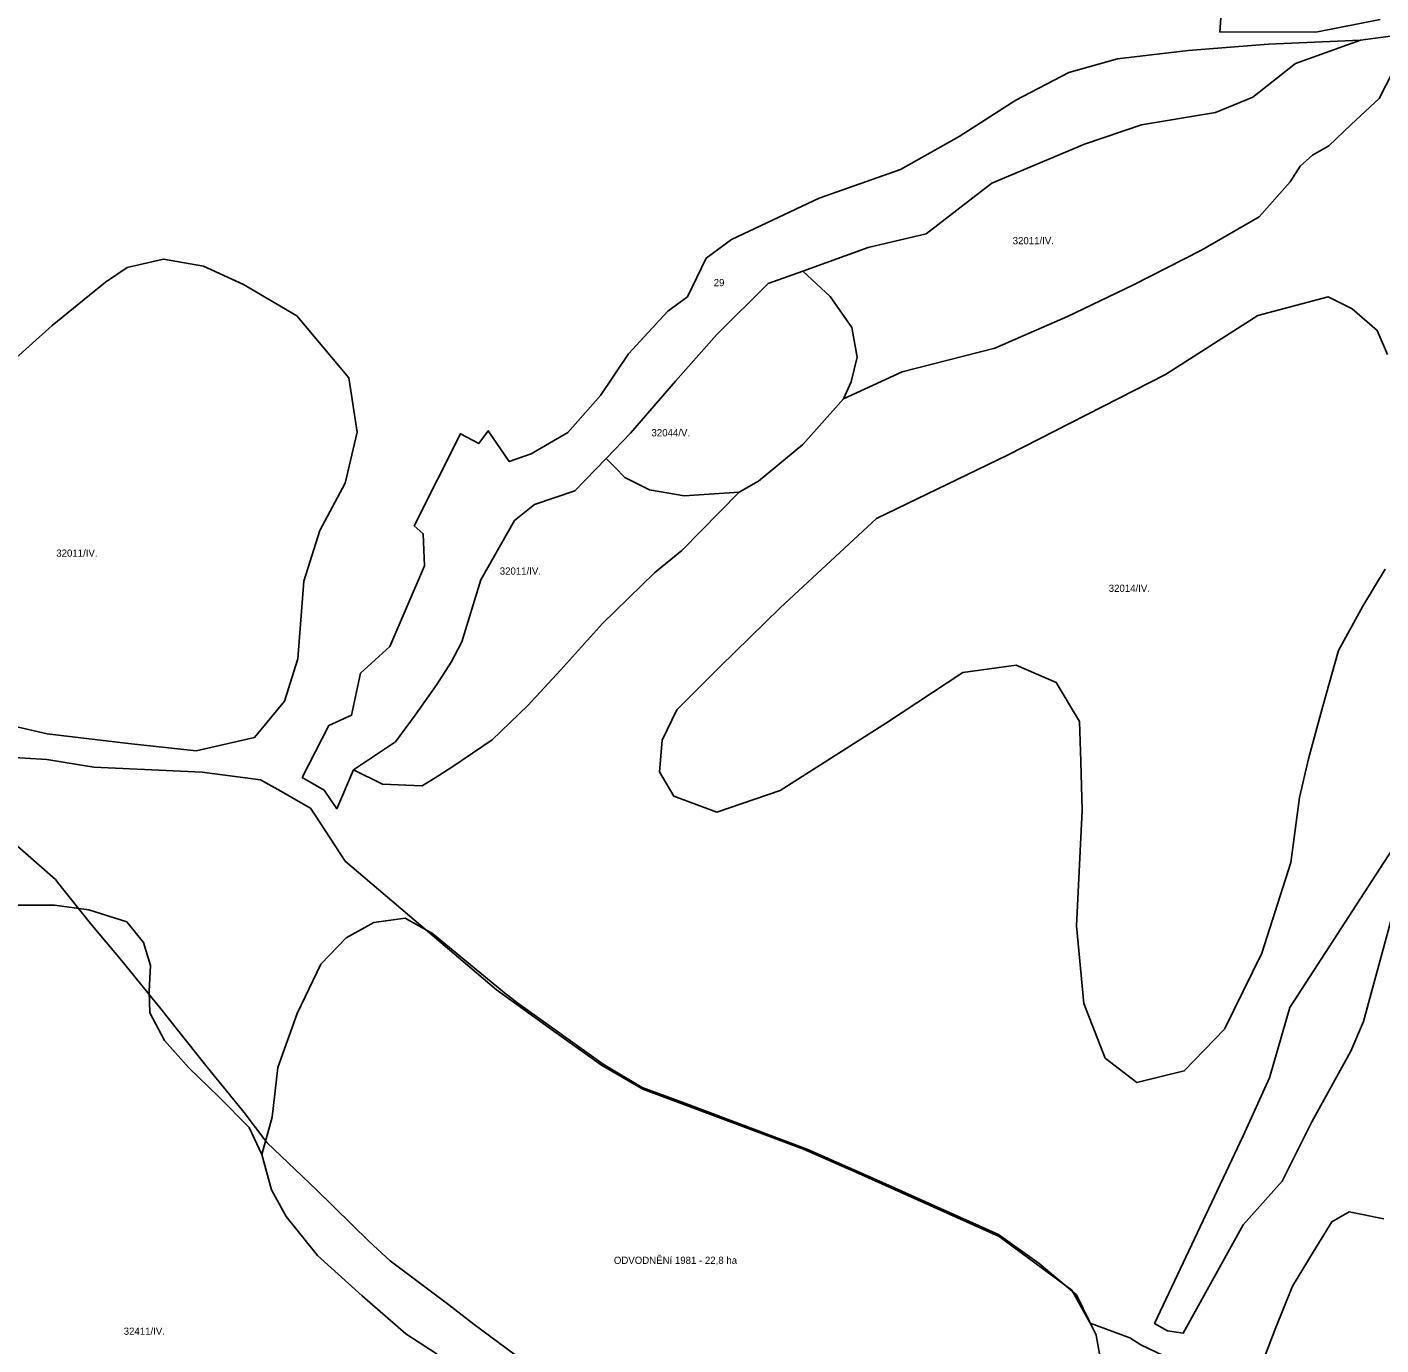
# Model space of a CAD drawing. Extents: x -521621 to -516761, y -1190184 to -1184927.
# Drawn here: x -518211 to -517460, y -1187665 to -1186934 of the extents above; entities that cross this region are included whole.
import ezdxf

# ---------------------------------------------------------------- set-up
doc = ezdxf.new("R2010")
doc.units = 0
doc.layers.add('BPEJ_s', color=7, linetype='Continuous')
doc.layers.add('odvodneni_s', color=7, linetype='Continuous')

msp = doc.modelspace()

# ---------------------------------------------------------------- linework, layer by layer
at = {"layer": 'BPEJ_s'}
for points in [[(-517449.03, -1186951.31), (-517460.58, -1186973.53), (-517476.03, -1186988.1), (-517488.46, -1186999.83), (-517497.52, -1187004.99), (-517504.38, -1187011.23), (-517509.98, -1187019.85), (-517527.2, -1187039.23), (-517559.06, -1187057.76), (-517597.31, -1187077.14), (-517633.59, -1187094.62), (-517673.9, -1187112.1), (-517725.3, -1187125.21), (-517757.89, -1187140.33), (-517780.4, -1187165.55), (-517804.92, -1187186.05), (-517815.67, -1187192.1), (-517847.58, -1187224.37), (-517862.7, -1187236.81), (-517891.59, -1187265.04), (-517914.77, -1187290.93), (-517932.91, -1187310.42), (-517952.73, -1187329.58), (-517974.57, -1187344.37), (-517982.97, -1187349.75), (-517991.7, -1187355.13), (-518013.54, -1187354.12), (-518029.72, -1187346.19), (-518038.98, -1187367.79), (-518045.96, -1187357.39), (-518058.12, -1187350.38), (-518043.45, -1187321.5), (-518030.79, -1187315.94), (-518025.93, -1187292.6), (-518009.65, -1187277.77), (-517990.31, -1187233), (-517991.03, -1187215.19), (-517996.11, -1187210.68), (-517970.35, -1187159.68), (-517960.2, -1187165.13), (-517954.93, -1187157.98), (-517943.27, -1187175.11), (-517931.05, -1187170.78), (-517910.74, -1187158.92), (-517892.69, -1187138.41), (-517877.03, -1187115.33), (-517855.2, -1187091.6), (-517844.41, -1187083.69), (-517834, -1187062.21), (-517819.95, -1187051.92), (-517771.39, -1187028.94), (-517726.14, -1187013.04), (-517693.57, -1186994.78), (-517662.24, -1186974.5), (-517632.81, -1186959.09), (-517605.84, -1186951.66), (-517566.49, -1186946.97), (-517521.9, -1186943.39), (-517470.99, -1186941.19), (-517445.99, -1186937.81)], [(-517449.03, -1186951.31), (-517460.58, -1186973.53), (-517476.03, -1186988.1), (-517488.46, -1186999.83), (-517497.52, -1187004.99), (-517504.38, -1187011.23), (-517509.98, -1187019.85), (-517527.2, -1187039.23), (-517559.06, -1187057.76), (-517597.31, -1187077.14), (-517633.59, -1187094.62), (-517673.9, -1187112.1), (-517725.3, -1187125.21), (-517757.89, -1187140.33), (-517753.52, -1187130.92), (-517750.16, -1187117.14), (-517753.18, -1187100.67), (-517765.28, -1187083.53), (-517780.4, -1187069.41), (-517744.18, -1187056.27), (-517711.98, -1187048.8), (-517675.47, -1187020.56), (-517624, -1186999.04), (-517592.36, -1186988.3), (-517551.35, -1186981.41), (-517530.71, -1186972.87), (-517507.04, -1186954.14), (-517470.99, -1186941.19), (-517445.99, -1186937.81)], [(-518222.49, -1187122.52), (-518196.96, -1187099.66), (-518167.39, -1187075.46), (-518155.3, -1187067.39), (-518135.14, -1187062.69), (-518112.97, -1187066.72), (-518090.8, -1187076.81), (-518061.24, -1187094.29), (-518032.35, -1187128.57), (-518027.65, -1187158.82), (-518034.36, -1187187.06), (-518048.47, -1187213.28), (-518057.21, -1187241.51), (-518060.57, -1187284.54), (-518067.96, -1187308.07), (-518084.75, -1187328.24), (-518117, -1187335.63), (-518154.63, -1187331.6), (-518199.64, -1187326.22), (-518235.25, -1187318.15)], [(-518222.49, -1187122.52), (-518196.96, -1187099.66), (-518167.39, -1187075.46), (-518155.3, -1187067.39), (-518135.14, -1187062.69), (-518112.97, -1187066.72), (-518090.8, -1187076.81), (-518061.24, -1187094.29), (-518032.35, -1187128.57), (-518027.65, -1187158.82), (-518034.36, -1187187.06), (-518048.47, -1187213.28), (-518057.21, -1187241.51), (-518060.57, -1187284.54), (-518067.96, -1187308.07), (-518084.75, -1187328.24), (-518117, -1187335.63), (-518154.63, -1187331.6), (-518199.64, -1187326.22), (-518235.25, -1187318.15)], [(-517457.21, -1187234.78), (-517469.69, -1187255.33), (-517483.07, -1187279.92), (-517491.81, -1187310.79), (-517499.72, -1187340.02), (-517504.83, -1187361.61), (-517509.62, -1187397.54), (-517525.58, -1187447.85), (-517546.33, -1187490.17), (-517568.67, -1187513.33), (-517595.01, -1187519.72), (-517612.56, -1187506.14), (-517619.74, -1187487.78), (-517624.53, -1187475.8), (-517628.52, -1187432.68), (-517625.33, -1187368.8), (-517626.13, -1187341.65), (-517626.93, -1187319.29), (-517639.7, -1187297.73), (-517662.04, -1187288.14), (-517691.57, -1187292.14), (-517733.86, -1187320.08), (-517792.92, -1187357.61), (-517828.03, -1187369.59), (-517851.97, -1187360.81), (-517859.95, -1187347.23), (-517858.36, -1187329.67), (-517850.38, -1187312.9), (-517826.44, -1187288.94), (-517792.92, -1187256.2), (-517739.45, -1187206.69), (-517666.83, -1187171.56), (-517579.04, -1187126.84), (-517527.97, -1187094.1), (-517488.87, -1187083.72), (-517475.57, -1187090.31), (-517461.64, -1187102.35), (-517455.94, -1187115.66)], [(-517455.94, -1187115.66), (-517461.64, -1187102.35), (-517475.57, -1187090.31), (-517488.87, -1187083.72), (-517527.97, -1187094.1), (-517579.04, -1187126.84), (-517666.83, -1187171.56), (-517739.45, -1187206.69), (-517792.92, -1187256.2), (-517826.44, -1187288.94), (-517850.38, -1187312.9), (-517858.36, -1187329.67), (-517859.95, -1187347.23), (-517851.97, -1187360.81), (-517828.03, -1187369.59), (-517792.92, -1187357.61), (-517733.86, -1187320.08), (-517691.57, -1187292.14), (-517662.04, -1187288.14), (-517639.7, -1187297.73), (-517626.93, -1187319.29), (-517626.13, -1187341.65), (-517625.33, -1187368.8), (-517628.52, -1187432.68), (-517624.53, -1187475.8), (-517619.74, -1187487.78), (-517612.56, -1187506.14), (-517595.01, -1187519.72), (-517568.67, -1187513.33), (-517546.33, -1187490.17), (-517525.58, -1187447.85), (-517509.62, -1187397.54), (-517504.83, -1187361.61), (-517499.72, -1187340.02), (-517491.81, -1187310.79), (-517483.07, -1187279.92), (-517469.69, -1187255.33), (-517457.21, -1187234.78)], [(-517451.95, -1187422.51), (-517469.3, -1187485.9), (-517476.24, -1187502.4), (-517497.93, -1187541.48), (-517514.42, -1187574.48), (-517536.11, -1187598.79), (-517569.29, -1187658.8), (-517578.06, -1187657.49), (-517585.17, -1187653.55), (-517536.11, -1187549.29), (-517521.36, -1187517.16), (-517510.08, -1187478.08), (-517399, -1187306.68)], [(-517399, -1187306.68), (-517510.08, -1187478.08), (-517521.36, -1187517.16), (-517536.11, -1187549.29), (-517585.17, -1187653.55), (-517578.06, -1187657.49), (-517569.29, -1187658.8), (-517536.11, -1187598.79), (-517514.42, -1187574.48), (-517497.93, -1187541.48), (-517476.24, -1187502.4), (-517469.3, -1187485.9), (-517451.95, -1187422.51)], [(-518219.49, -1187421.38), (-518195.69, -1187421.38), (-518176.51, -1187423.87), (-518155.55, -1187430.62), (-518146.31, -1187442), (-518142.41, -1187454.79), (-518143.12, -1187469.01), (-518142.76, -1187481.09), (-518134.59, -1187496.38), (-518121.09, -1187511.66), (-518104.4, -1187527.66), (-518087.7, -1187544.72), (-518080.6, -1187559.65), (-518075.27, -1187579.19), (-518067.1, -1187594.12), (-518049.7, -1187615.8), (-518024.83, -1187638.2), (-518000.68, -1187659.17), (-517983.27, -1187670.54)], [(-517612.9, -1187685.91), (-517617.66, -1187660.01), (-517628.56, -1187637.52), (-517649.24, -1187620.23), (-517671.84, -1187604.16), (-517736.22, -1187575.2), (-517777.6, -1187556.89), (-517845.83, -1187531.14), (-517869.6, -1187522.41), (-517891.18, -1187509.56), (-517938.45, -1187475.62), (-517945.94, -1187470), (-517985.88, -1187436.93), (-518001.03, -1187428.49), (-518018.44, -1187430.98), (-518033.71, -1187439.51), (-518047.92, -1187454.08), (-518061.06, -1187481.45), (-518071.72, -1187511.31), (-518074.92, -1187539.03), (-518080.6, -1187559.65), (-518087.7, -1187544.72), (-518104.4, -1187527.66), (-518121.09, -1187511.66), (-518134.59, -1187496.38), (-518142.76, -1187481.09), (-518143.12, -1187469.01), (-518142.41, -1187454.79), (-518146.31, -1187442), (-518155.55, -1187430.62), (-518176.51, -1187423.87), (-518195.69, -1187421.38), (-518219.49, -1187421.38)], [(-517983.27, -1187670.54), (-518000.68, -1187659.17), (-518024.83, -1187638.2), (-518049.7, -1187615.8), (-518067.1, -1187594.12), (-518075.27, -1187579.19), (-518080.6, -1187559.65), (-518074.92, -1187539.03), (-518071.72, -1187511.31), (-518061.06, -1187481.45), (-518047.92, -1187454.08), (-518033.71, -1187439.51), (-518018.44, -1187430.98), (-518001.03, -1187428.49), (-517985.88, -1187436.93), (-517945.94, -1187470), (-517938.45, -1187475.62), (-517891.18, -1187509.56), (-517869.6, -1187522.41), (-517845.83, -1187531.14), (-517777.6, -1187556.89), (-517736.22, -1187575.2), (-517671.84, -1187604.16), (-517649.24, -1187620.23), (-517628.56, -1187637.52), (-517617.66, -1187660.01), (-517612.9, -1187685.91)], [(-517540.69, -1187715.22), (-517518.21, -1187656.6), (-517508.68, -1187632.75), (-517497.2, -1187613.83), (-517486.81, -1187597.03), (-517477.21, -1187591.43), (-517458.02, -1187595.43)], [(-517458.02, -1187595.43), (-517477.21, -1187591.43), (-517486.81, -1187597.03), (-517497.2, -1187613.83), (-517508.68, -1187632.75), (-517518.21, -1187656.6), (-517540.69, -1187715.22)]]:
    msp.add_lwpolyline(points, dxfattribs=at)
for points in [[(-518029.72, -1187346.19), (-518038.98, -1187367.79), (-518045.96, -1187357.39), (-518058.12, -1187350.38), (-518043.45, -1187321.5), (-518030.79, -1187315.94), (-518025.93, -1187292.6), (-518009.65, -1187277.77), (-517990.31, -1187233), (-517991.03, -1187215.19), (-517996.11, -1187210.68), (-517970.35, -1187159.68), (-517960.2, -1187165.13), (-517954.93, -1187157.98), (-517943.27, -1187175.11), (-517931.05, -1187170.78), (-517910.74, -1187158.92), (-517892.69, -1187138.41), (-517877.03, -1187115.33), (-517855.2, -1187091.6), (-517844.41, -1187083.69), (-517834, -1187062.21), (-517819.95, -1187051.92), (-517771.39, -1187028.94), (-517726.14, -1187013.04), (-517693.57, -1186994.78), (-517662.24, -1186974.5), (-517632.81, -1186959.09), (-517605.84, -1186951.66), (-517566.49, -1186946.97), (-517521.9, -1186943.39), (-517470.99, -1186941.19), (-517507.04, -1186954.14), (-517530.71, -1186972.87), (-517551.35, -1186981.41), (-517592.36, -1186988.3), (-517624, -1186999.04), (-517675.47, -1187020.56), (-517711.98, -1187048.8), (-517744.18, -1187056.27), (-517780.4, -1187069.41), (-517799.61, -1187076.37), (-517828.16, -1187104.61), (-517851.06, -1187130.52), (-517875.94, -1187159.33), (-517889.51, -1187173.34), (-517906.94, -1187191.35), (-517929.34, -1187198.96), (-517940.34, -1187207.76), (-517959.14, -1187240.79), (-517969.54, -1187275.21), (-517975.54, -1187286.42), (-517983.54, -1187298.83), (-517995.59, -1187315.89), (-518006.5, -1187330.73)], [(-517889.51, -1187173.34), (-517875.94, -1187159.33), (-517851.06, -1187130.52), (-517828.16, -1187104.61), (-517799.61, -1187076.37), (-517780.4, -1187069.41), (-517765.28, -1187083.53), (-517753.18, -1187100.67), (-517750.16, -1187117.14), (-517753.52, -1187130.92), (-517757.89, -1187140.33), (-517780.4, -1187165.55), (-517804.92, -1187186.05), (-517815.67, -1187192.1), (-517846.24, -1187194.12), (-517865.39, -1187190.76), (-517879.16, -1187184.03), (-517884.54, -1187178.32)], [(-518029.72, -1187346.19), (-518006.5, -1187330.73), (-517995.59, -1187315.89), (-517983.54, -1187298.83), (-517975.54, -1187286.42), (-517969.54, -1187275.21), (-517959.14, -1187240.79), (-517940.34, -1187207.76), (-517929.34, -1187198.96), (-517906.94, -1187191.35), (-517889.51, -1187173.34), (-517884.54, -1187178.32), (-517879.16, -1187184.03), (-517865.39, -1187190.76), (-517846.24, -1187194.12), (-517815.67, -1187192.1), (-517847.58, -1187224.37), (-517862.7, -1187236.81), (-517891.59, -1187265.04), (-517914.77, -1187290.93), (-517932.91, -1187310.42), (-517952.73, -1187329.58), (-517974.57, -1187344.37), (-517982.97, -1187349.75), (-517991.7, -1187355.13), (-518013.54, -1187354.12)]]:
    msp.add_lwpolyline(points, close=True, dxfattribs=at)
at = {"layer": 'odvodneni_s'}
for points in [[(-517543.45, -1186858.01), (-517548.94, -1186936.72), (-517494.86, -1186936.67), (-517460.04, -1186929.71)], [(-518195.14, -1187407), (-518237.7, -1187369.82), (-518236.16, -1187338.27), (-518199.87, -1187340.38), (-518173.8, -1187344.62), (-518113.74, -1187347.57), (-518081.32, -1187351.71), (-518067.11, -1187359.78)], [(-518067.11, -1187359.78), (-518063.05, -1187362.09), (-518053.59, -1187367.46), (-518051.08, -1187371.3)], [(-518051.08, -1187371.3), (-518034.34, -1187396.85)], [(-518034.34, -1187396.85), (-517950.34, -1187468.33)], [(-518191.26, -1187411.98), (-518193.24, -1187409.43), (-518195.14, -1187407)], [(-518175.58, -1187431.48), (-518191.26, -1187411.98)], [(-518158.37, -1187452.16), (-518175.58, -1187431.48)], [(-518137.31, -1187477.94), (-518158.37, -1187452.16)], [(-517950.34, -1187468.33), (-517921.14, -1187489.42)], [(-518111.61, -1187510.19), (-518137.31, -1187477.94)], [(-517921.14, -1187489.42), (-517892.03, -1187510.14)], [(-518090.47, -1187536.35), (-518111.61, -1187510.19)], [(-517892.03, -1187510.14), (-517869.1, -1187523.41)], [(-517869.1, -1187523.41), (-517829.03, -1187538.42)], [(-518077.74, -1187553.09), (-518090.47, -1187536.35)], [(-517829.03, -1187538.42), (-517780.02, -1187556.66)], [(-518050.19, -1187579.33), (-518077.74, -1187553.09)], [(-517780.02, -1187556.66), (-517749.26, -1187570.2)], [(-517749.26, -1187570.2), (-517671.43, -1187605.2)], [(-518020.95, -1187608.03), (-518050.19, -1187579.33)], [(-517671.43, -1187605.2), (-517631.17, -1187634.96)], [(-518009.37, -1187618.6), (-518020.95, -1187608.03)], [(-517976.81, -1187643.14), (-518009.37, -1187618.6)], [(-517631.17, -1187634.96), (-517620.95, -1187653.19)], [(-517962.84, -1187653.94), (-517976.81, -1187643.14)], [(-517940, -1187670.92), (-517962.84, -1187653.94)], [(-517620.95, -1187653.19), (-517598.93, -1187661.48), (-517592.76, -1187665.26), (-517580.33, -1187671.15), (-517572.04, -1187673.09), (-517601.22, -1187736.39), (-517633.65, -1187806.72), (-517653.69, -1187806.18), (-517693.66, -1187793.99)]]:
    msp.add_lwpolyline(points, dxfattribs=at)

# ---------------------------------------------------------------- texts
at = {"layer": 'BPEJ_s'}
for s, p in [('32011/IV.', (-517663.93, -1187054.51)), ('29', (-517829.83, -1187077.78)), ('32044/V.', (-517864.36, -1187161.1)), ('32011/IV.', (-518194.66, -1187227.91)), ('32011/IV.', (-517948.56, -1187237.85)), ('32014/IV.', (-517610.63, -1187247.43)), ('32411/IV.', (-518157.25, -1187659.74))]:
    msp.add_text(s, height=4, dxfattribs=at).set_placement(p)
at = {"layer": 'odvodneni_s'}
msp.add_text('ODVODNĚNí 1981 - 22,8 ha', height=4, dxfattribs=at).set_placement((-517885.24, -1187620.39))

doc.saveas('drawing.dxf')
